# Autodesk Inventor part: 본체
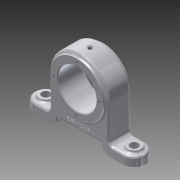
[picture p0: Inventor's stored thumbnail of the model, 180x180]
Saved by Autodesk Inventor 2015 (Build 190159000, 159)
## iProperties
Created: 2019-05
Part Number: 본체
Material: 알루미늄 6061
Document SubType Name: Modeling
Designer: now
Density: 2.7 g/cm^3
Appearance: 알루미늄 - 평지
Mass: 454.998 g
Surface Area: 321.963 cm^2
Volume: 168.518 cm^3
Author: now
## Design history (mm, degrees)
sketch "스케치2"
  geometry: L1 (75, -15)-(-75, -15); L2 (-75, -15)-(-75, 15); L3 (-75, 15)-(75, 15); L4 (75, 15)-(75, -15); L5 (75, -15)-(-75, 15); L6 (-75, -15)-(75, 15); 1 further point
  constraints: 12 end point, 2 midpoint, 2 parallel, 1 horizontal, 1 perpendicular
  dimensions: "d0" = 150 distance of L1.start L1.end; "d1" = 30 distance of L1.end L2.end
extrude "돌출1" new body sketch "스케치2" distance "d2" = 12; taper "d3" = 0 deg
sketch "스케치3"
  geometry: C1 r 9 at (-60, 0); C2 r 9 at (60, 0); 1 further point
  constraints: 2 centre point, 2 horizontal alignment
  dimensions: "d4" = 18 diameter of C1; "d5" = 18 diameter of C2; "d6" = 120 distance of C2.centre C1.centre; "d7" = 60 distance of C1.centre point (0, 0)
extrude "돌출2" join sketch "스케치3" distance "d8" = 3; taper "d9" = 0 deg
fillet "모깎기1" dims "d10" = 15
sketch "스케치5"
  geometry: L1 (-69, 12)-(-69, 15) reference; L2 (-69, 15)-(-51, 15) reference; L3 (-51, 15)-(-51, 12) reference; L4 (-51, 12)-(51, 12) reference; L5 (51, 12)-(51, 15) reference; L6 (51, 15)-(69, 15) reference; L7 (69, 15)-(69, 12) reference; L8 (69, 12)-(75, 12) reference; L9 (75, 12)-(75, 0) reference; L10 (75, 0)-(-75, 0) reference; L11 (-75, 0)-(-75, 12) reference; L12 (-75, 12)-(-69, 12) reference; C1 r 40 at (0, 60); 2 further points
  constraints: 1 centre point, 1 midpoint, 1 vertical alignment
  dimensions: "d11" = 80 diameter of C1; "d12" = 60 distance from line of L10 C1.centre
extrude "돌출3" join sketch "스케치5" stored distance "d13" = 30; taper "d14" = 0 deg
sketch "스케치6"
  geometry: L1 (-60, -15)-(60, -15) reference; L2 (-40, 15)-(40, 15); L3 (40, 15)-(40, -15); L4 (40, -15)-(-40, -15); L5 (-40, -15)-(-40, 15); L6 (-40, 15)-(40, -15); L7 (40, 15)-(-40, -15); 1 further point
  constraints: 12 end point, 2 midpoint, 2 parallel, 1 horizontal, 1 perpendicular, 1 point on line
  dimensions: "d15" = 80 distance between parallel lines of L5 L3
extrude "돌출4" join sketch "스케치6" stored distance "d16" = 0; taper "d17" = 0 deg
sketch "스케치7"
  geometry: L1 (120, 0)-(0, 0) reference; L2 (96, 4)-(24, 4); L3 (24, 4)-(24, 0); L4 (24, 0)-(96, 0); L5 (96, 0)-(96, 4); 2 further points
  constraints: 8 end point, 2 midpoint, 2 parallel, 1 horizontal, 1 perpendicular
  dimensions: "d18" = 72 distance between parallel lines of L5 L3; "d19" = 4 distance between parallel lines of L1 L2
extrude "돌출5" cut sketch "스케치7" stored distance "d20" = 36; taper "d21" = 0 deg
sketch "스케치8"
  geometry: L1 (-96, 4)-(-24, 4) reference; L2 (-90, 10)-(-30, 10); L3 (-30, 10)-(-30, 4); L4 (-30, 4)-(-90, 4); L5 (-90, 4)-(-90, 10); 2 further points
  constraints: 8 end point, 2 midpoint, 2 parallel, 1 horizontal, 1 perpendicular
  dimensions: "d22" = 6 distance between parallel lines of L4 L2; "d23" = 60 distance between parallel lines of L3 L5
extrude "돌출6" cut sketch "스케치8" stored distance "d24" = 36; taper "d25" = 0 deg
sketch "스케치10"
  geometry: C1 r 26 at (-60, 60); A1 r 40 centre (-60, 60) between (-20, 60) and (-100, 60) reference; 1 further point
  constraints: 1 centre point, 1 coincident
  dimensions: "d26" = 52 diameter of C1
extrude "돌출7" cut sketch "스케치10" stored distance "d27" = 36; taper "d28" = 0 deg
sketch "스케치11"
  geometry: C1 r 26 at (-60, 60) reference; C2 r 36 at (-60, 60); A1 r 40 centre (-60, 60) between (-20, 60) and (-100, 60) reference; 1 further point
  constraints: 1 centre point, 1 coincident
  dimensions: "d29" = 72 diameter of C2
extrude "돌출8" join sketch "스케치11" distance "d30" = 3; taper "d31" = 0 deg
sketch "스케치12"
  geometry: C1 r 26 at (0, 0) reference; 2 further points
  constraints: 1 vertical alignment
  dimensions: "d32" = 31 distance of point (0, 31) C1.centre
hole "구멍1" sketch "스케치12" at (0, 31) diameter "d33" = 3.242; stored, may be unused: countersink angle "d37" = 90 deg, drill point angle "d39" = 118 deg; dims "d34" = 8, "d35" = 4, "d36" = 2, "d38" = 11.8
node "작업 평면1"
sketch "스케치13"
  geometry: 1 further point
hole "구멍2" sketch "스케치13" at (0, 0) diameter "d44" = 4.917; stored, may be unused: countersink angle "d48" = 90 deg, drill point angle "d50" = 118 deg; dims "d45" = 8, "d46" = 7, "d47" = 1, "d49" = 10
sketch "스케치14"
  geometry: C1 r 3.5 at (0, 0) reference
hole "구멍3" sketch "스케치14" at (0, 0) diameter "d51" = 2; stored, may be unused: countersink angle "d55" = 90 deg, drill point angle "d57" = 118 deg; dims "d52" = 8, "d53" = 7, "d54" = 1, "d56" = 30
hole "구멍4" diameter "d60" = 11; stored, may be unused: countersink angle "d64" = 90 deg, drill point angle "d66" = 118 deg; dims "d58" = 10, "d59" = 10, "d61" = 8, "d62" = 7, "d63" = 1, "d65" = 30
chamfer "모따기1" distance "d67" = 1; stored, may be unused: second distance "d68" = 2, angle "d69" = 45 deg
fillet "모깎기2" dims "d70" = 6
fillet "모깎기3" dims "d71" = 3
fillet "모깎기4" dims "d72" = 3
fillet "모깎기5" dims "d73" = 3
sketch "스케치15"
  geometry: C1 r 1.5 at (0, -26); A1 r 36 centre (0, 0) between (-34.154, 11.38) and (34.154, 11.38) reference; 2 further points
  constraints: 2 vertical alignment, 1 centre point, 1 other
  dimensions: "d74" = 3 diameter of C1
extrude "돌출9" cut sketch "스케치15" stored distance "d75" = 3; taper "d76" = 0 deg
sketch "스케치16"
  geometry: L1 (-63, 10)-(-9, 10) reference; A1 r 3 centre (-9, 7) between (-6, 7) and (-9, 10) reference; 3 further points
  constraints: 1 other
  dimensions: "d77" = 7 distance from line of point (-36, 17) L1; "d78" = 30 horizontal distance of point (-6, 4) point (-36, 17)
feature "엠보싱1" sketch "스케치16" dims "d0" = 150, "d1" = 30, "d79" = 0.5, "d80" = 0
node "솔리드1"
mirror "대칭1"
pattern_circular "원형 패턴1" dims angle "d41" = 360 deg
mirror "대칭2"
mirror "대칭3"
node "절단 모서리 투영1"
